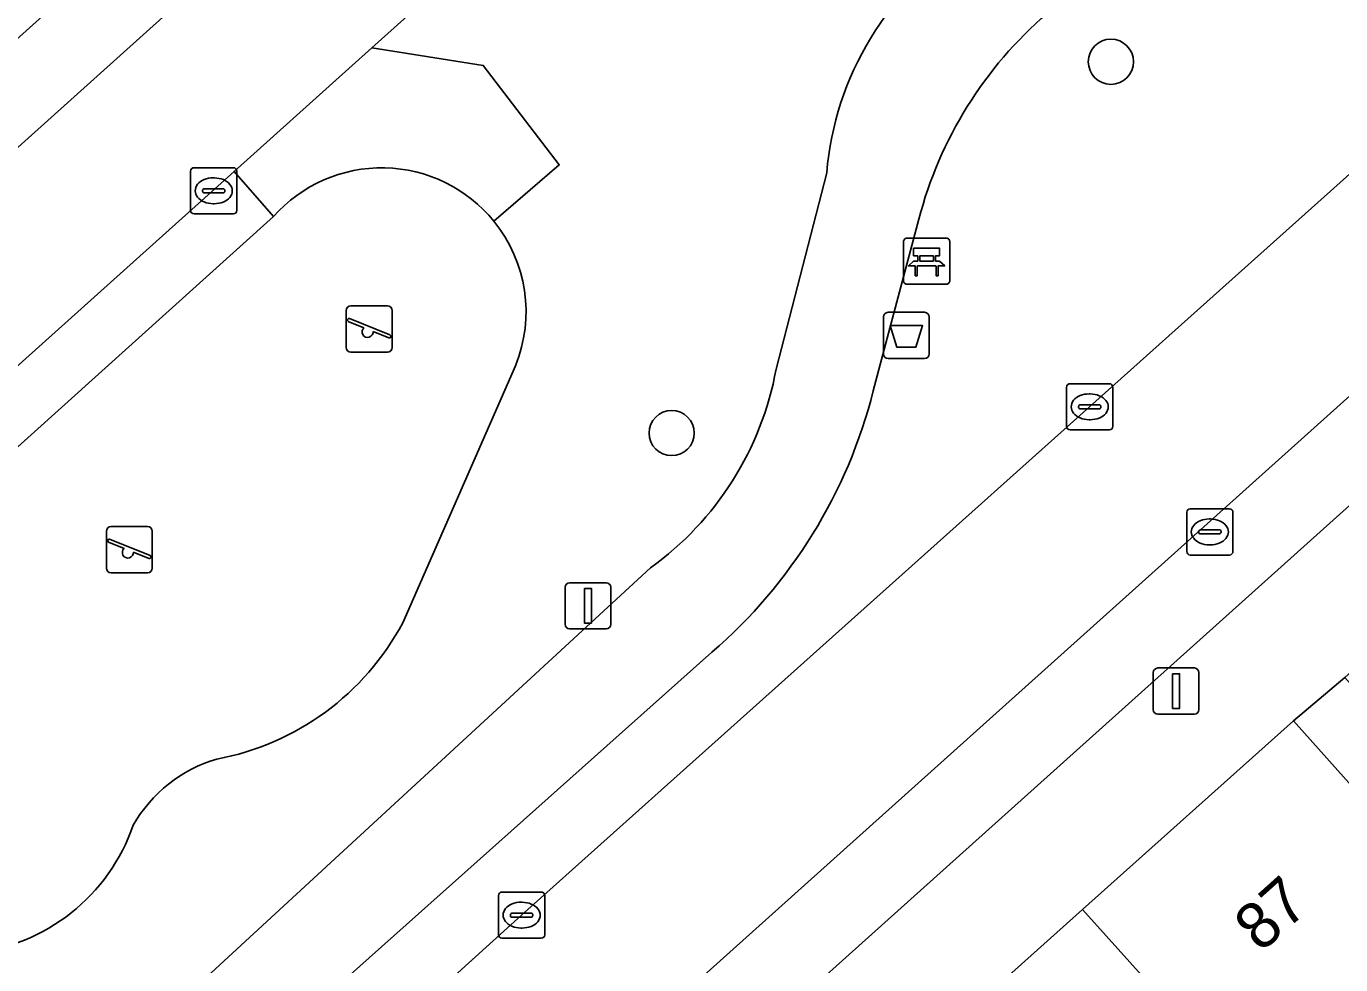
# Model space of a CAD drawing. Extents: x 162172 to 163187, y 382874 to 383685.
# Drawn here: x 162755.23 to 162783.66, y 383328.11 to 383348.42 of the extents above; entities that cross this region are included whole.
import ezdxf

# ---------------------------------------------------------------- set-up
doc = ezdxf.new("R2010")
doc.units = 0
for name, color, linetype in [('IMGEO_Afvalbak', 7, 'Continuous'), ('IMGEO_Bank', 7, 'Continuous'), ('IMGEO_Berm_groen', 7, 'Continuous'), ('IMGEO_Boom', 7, 'Continuous'), ('IMGEO_Groenvoorziening', 7, 'Continuous'), ('IMGEO_Haag', 7, 'Continuous'), ('IMGEO_Kolk', 7, 'Continuous'), ('IMGEO_Lichtmast', 7, 'Continuous'), ('IMGEO_Pand', 7, 'Continuous'), ('IMGEO_Pand_nummerreeks', 7, 'Continuous'), ('IMGEO_Parkeervlak_open', 7, 'Continuous'), ('IMGEO_Rijbaan_lokaal_open', 7, 'Continuous'), ('IMGEO_Speelvoorziening', 7, 'Continuous'), ('IMGEO_Terreindeel_zand', 7, 'Continuous'), ('IMGEO_Voetpad_halfverhard', 7, 'Continuous'), ('IMGEO_Voetpad_open', 7, 'Continuous')]:
    doc.layers.add(name, color=color, linetype=linetype)

msp = doc.modelspace()

# ---------------------------------------------------------------- linework, layer by layer
at = {"layer": 'IMGEO_Afvalbak'}
for p, q in [((162773.773, 383341.333), (162773.773, 383342.133)), ((162773.773, 383342.133), (162773.773, 383341.333)), ((162773.873, 383342.233), (162774.663, 383342.233)), ((162774.663, 383342.233), (162773.873, 383342.233)), ((162774.763, 383342.133), (162774.763, 383341.333)), ((162774.763, 383341.333), (162774.763, 383342.133)), ((162774.663, 383341.233), (162773.873, 383341.233)), ((162773.873, 383341.233), (162774.663, 383341.233))]:
    msp.add_line(p, q, dxfattribs=at)
msp.add_lwpolyline([(162773.916, 383341.947), (162774.62, 383341.947), (162774.471, 383341.477), (162774.065, 383341.477), (162773.916, 383341.947)], dxfattribs=at)
for centre, start, end in [((162773.873, 383342.133), 90, 180), ((162773.873, 383342.133), 90, 180), ((162774.663, 383342.133), 0, 90), ((162774.663, 383342.133), 360, 90), ((162773.873, 383341.333), 180, 270), ((162773.873, 383341.333), 180, 270), ((162774.663, 383341.333), 270, 0), ((162774.663, 383341.333), 270, 0)]:
    msp.add_arc(centre, 0.1, start, end, dxfattribs=at)
at = {"layer": 'IMGEO_Bank'}
for p, q in [((162774.282, 383343.84), (162775.123, 383343.84)), ((162775.123, 383343.84), (162774.282, 383343.84)), ((162774.207, 383342.915), (162774.207, 383343.756)), ((162774.207, 383343.756), (162774.207, 383342.915)), ((162775.207, 383343.765), (162775.207, 383342.924)), ((162775.207, 383342.924), (162775.207, 383343.765)), ((162774.904, 383343.238), (162774.511, 383343.238)), ((162774.516, 383343.346), (162774.516, 383343.452)), ((162774.56, 383343.452), (162774.56, 383343.346)), ((162774.848, 383343.458), (162774.566, 383343.458)), ((162774.566, 383343.34), (162774.848, 383343.34)), ((162774.854, 383343.346), (162774.854, 383343.452)), ((162774.898, 383343.452), (162774.898, 383343.346)), ((162775.132, 383342.84), (162774.291, 383342.84)), ((162774.291, 383342.84), (162775.132, 383342.84))]:
    msp.add_line(p, q, dxfattribs=at)
for points in [[(162774.51, 383343.458), (162774.424, 383343.458), (162774.424, 383343.619), (162774.987, 383343.619), (162774.987, 383343.458), (162774.904, 383343.458)], [(162774.454, 383343.238), (162774.312, 383343.238), (162774.424, 383343.34), (162774.51, 383343.34)], [(162774.504, 383343.231), (162774.504, 383343.024), (162774.461, 383343.024), (162774.461, 383343.231)], [(162774.904, 383343.34), (162774.987, 383343.34), (162775.099, 383343.238), (162774.96, 383343.238)], [(162774.954, 383343.231), (162774.954, 383343.024), (162774.91, 383343.024), (162774.91, 383343.231)]]:
    msp.add_lwpolyline(points, dxfattribs=at)
for centre, radius, start, end in [((162774.285, 383343.762), 0.0779, 92.4484, 184.2845), ((162774.285, 383343.762), 0.0779, 92.4484, 184.2845), ((162775.129, 383343.762), 0.0779, 2.4484, 94.2845), ((162775.129, 383343.762), 0.0779, 2.4484, 94.2845), ((162774.454, 383343.231), 0.00671, 2.8957, 87.1043), ((162774.511, 383343.231), 0.00671, 92.8957, 177.1043), ((162774.509, 383343.451), 0.00671, 2.8957, 87.1043), ((162774.509, 383343.347), 0.00671, 272.8957, 357.1043), ((162774.566, 383343.451), 0.00671, 92.8957, 177.1043), ((162774.566, 383343.347), 0.00671, 182.8957, 267.1043), ((162774.848, 383343.451), 0.00671, 2.8957, 87.1043), ((162774.848, 383343.347), 0.00671, 272.8957, 357.1043), ((162774.905, 383343.451), 0.00671, 92.8957, 177.1043), ((162774.905, 383343.347), 0.00671, 182.8957, 267.1043), ((162774.903, 383343.231), 0.00671, 2.8957, 87.1043), ((162774.96, 383343.231), 0.00671, 92.8957, 177.1043), ((162774.285, 383342.918), 0.0779, 182.4484, 274.2845), ((162774.285, 383342.918), 0.0779, 182.4484, 274.2845), ((162775.129, 383342.918), 0.0779, 272.4484, 4.2845), ((162775.129, 383342.918), 0.0779, 272.4484, 4.2845)]:
    msp.add_arc(centre, radius, start, end, dxfattribs=at)
at = {"layer": 'IMGEO_Berm_groen'}
for points in [[(162744.611, 383310), (162750.185, 383314.921), (162765.945, 383329.187), (162788.183, 383349.104), (162785.604, 383352.953), (162793.329, 383359.988), (162800.361, 383366.393), (162802.051, 383364.873), (162802.602, 383364.378)], [(162767.014, 383351.829), (162765.744, 383350.688), (162762.702, 383347.957), (162765.113, 383347.576), (162766.759, 383345.424), (162765.345, 383344.203)], [(162765.113, 383347.576), (162762.702, 383347.957), (162759.725, 383345.284), (162760.577, 383344.304)], [(162765.345, 383344.203), (162766.759, 383345.424), (162765.113, 383347.576)], [(162771.45, 383341.002), (162772.546, 383345.251)], [(162774.537, 383344.248), (162773.553, 383340.531)], [(162765.813, 383341.076), (162763.374, 383335.515)], [(162752.484, 383321.73), (162768.734, 383336.704)], [(162770.061, 383334.875), (162753.755, 383320.332)]]:
    msp.add_lwpolyline(points, dxfattribs=at)
for centre, radius, start, end in [((162779.19, 383344.699), 6.667, 122.1655, 175.2507), ((162783.057, 383342.031), 8.803, 130.7348, 165.4165), ((162762.918, 383342.241), 3.12, 38.9519, 138.6211), ((162762.923, 383342.242), 3.117, 338.0322, 38.9917), ((162764.766, 383342.219), 6.794, 305.7361, 349.6845), ((162762.811, 383343.257), 11.082, 310.8576, 345.7602), ((162758.299, 383338.215), 5.748, 280.5403, 331.9821), ((162760.223, 383329.601), 3.089, 106.4034, 150.2015), ((162753.628, 383332.479), 4.139, 210.3244, 341.0695)]:
    msp.add_arc(centre, radius, start, end, dxfattribs=at)
at = {"layer": 'IMGEO_Boom'}
for centre in [(162778.692, 383347.656), (162769.191, 383339.62)]:
    msp.add_circle(centre, 0.489, dxfattribs=at)
at = {"layer": 'IMGEO_Groenvoorziening'}
msp.add_lwpolyline([(162760.577, 383344.304), (162759.725, 383345.284), (162749.865, 383336.431), (162750.744, 383335.448)], close=True, dxfattribs=at)
at = {"layer": 'IMGEO_Haag'}
msp.add_lwpolyline([(162760.577, 383344.304), (162759.725, 383345.284), (162749.865, 383336.431), (162750.744, 383335.448)], close=True, dxfattribs=at)
at = {"layer": 'IMGEO_Kolk'}
for p, q in [((162758.784, 383344.437), (162758.784, 383345.289)), ((162758.859, 383345.363), (162759.711, 383345.363)), ((162759.785, 383345.289), (162759.785, 383344.437)), ((162759.272, 383345.143), (162759.297, 383345.143)), ((162759.043, 383344.857), (162759.043, 383344.869)), ((162759.481, 383344.82), (162759.083, 383344.82)), ((162759.086, 383344.906), (162759.484, 383344.906)), ((162759.527, 383344.869), (162759.527, 383344.857)), ((162759.711, 383344.363), (162758.859, 383344.363)), ((162759.295, 383344.583), (162759.27, 383344.583)), ((162777.809, 383340.688), (162778.661, 383340.688)), ((162777.734, 383339.762), (162777.734, 383340.614)), ((162778.222, 383340.468), (162778.247, 383340.468)), ((162778.735, 383340.614), (162778.735, 383339.762)), ((162777.993, 383340.182), (162777.993, 383340.194)), ((162778.431, 383340.145), (162778.033, 383340.145)), ((162778.036, 383340.231), (162778.434, 383340.231)), ((162778.477, 383340.194), (162778.477, 383340.182)), ((162778.245, 383339.908), (162778.22, 383339.908)), ((162778.661, 383339.688), (162777.809, 383339.688)), ((162780.332, 383337.055), (162780.332, 383337.907)), ((162780.407, 383337.981), (162781.259, 383337.981)), ((162781.333, 383337.907), (162781.333, 383337.055)), ((162780.82, 383337.761), (162780.845, 383337.761)), ((162780.591, 383337.475), (162780.591, 383337.487)), ((162781.029, 383337.438), (162780.631, 383337.438)), ((162780.634, 383337.524), (162781.032, 383337.524)), ((162781.075, 383337.487), (162781.075, 383337.475)), ((162781.259, 383336.981), (162780.407, 383336.981)), ((162780.843, 383337.201), (162780.818, 383337.201)), ((162765.444, 383328.761), (162765.444, 383329.613)), ((162765.519, 383329.687), (162766.371, 383329.687)), ((162766.445, 383329.613), (162766.445, 383328.761)), ((162765.932, 383329.467), (162765.957, 383329.467)), ((162765.703, 383329.181), (162765.703, 383329.193)), ((162766.141, 383329.144), (162765.743, 383329.144)), ((162765.746, 383329.23), (162766.144, 383329.23)), ((162766.187, 383329.193), (162766.187, 383329.181)), ((162765.955, 383328.907), (162765.93, 383328.907)), ((162766.371, 383328.687), (162765.519, 383328.687))]:
    msp.add_line(p, q, dxfattribs=at)
for points in [[(162758.784, 383344.437), (162758.784, 383345.289)], [(162758.859, 383345.363), (162759.711, 383345.363)], [(162759.785, 383345.289), (162759.785, 383344.437)], [(162759.711, 383344.363), (162758.859, 383344.363)], [(162777.809, 383340.688), (162778.661, 383340.688)], [(162777.734, 383339.762), (162777.734, 383340.614)], [(162778.735, 383340.614), (162778.735, 383339.762)], [(162778.661, 383339.688), (162777.809, 383339.688)], [(162780.332, 383337.055), (162780.332, 383337.907)], [(162780.407, 383337.981), (162781.259, 383337.981)], [(162781.333, 383337.907), (162781.333, 383337.055)], [(162781.259, 383336.981), (162780.407, 383336.981)], [(162765.444, 383328.761), (162765.444, 383329.613)], [(162765.519, 383329.687), (162766.371, 383329.687)], [(162766.445, 383329.613), (162766.445, 383328.761)], [(162766.371, 383328.687), (162765.519, 383328.687)]]:
    msp.add_lwpolyline(points, dxfattribs=at)
for centre, radius, start, end in [((162758.861, 383345.287), 0.0765, 91.552, 178.448), ((162758.861, 383345.287), 0.0765, 91.552, 178.448), ((162759.709, 383345.287), 0.0765, 1.552, 88.448), ((162759.709, 383345.287), 0.0765, 1.552, 88.448), ((162759.083, 383344.866), 0.0403, 85.8775, 175.7526), ((162759.08, 383344.856), 0.0366, 178.938, 274.7102), ((162759.484, 383344.863), 0.043, 264.8664, 352.4533), ((162759.488, 383344.868), 0.0386, 1.7309, 96.639), ((162758.861, 383344.439), 0.0765, 181.552, 268.448), ((162758.861, 383344.439), 0.0765, 181.552, 268.448), ((162759.709, 383344.439), 0.0765, 271.552, 358.448), ((162759.709, 383344.439), 0.0765, 271.552, 358.448), ((162777.811, 383340.612), 0.0765, 91.552, 178.448), ((162777.811, 383340.612), 0.0765, 91.552, 178.448), ((162778.659, 383340.612), 0.0765, 1.552, 88.448), ((162778.659, 383340.612), 0.0765, 1.552, 88.448), ((162778.033, 383340.191), 0.0403, 85.8775, 175.7526), ((162778.03, 383340.181), 0.0366, 178.938, 274.7102), ((162778.434, 383340.188), 0.043, 264.8664, 352.4533), ((162778.438, 383340.193), 0.0386, 1.7309, 96.639), ((162777.811, 383339.764), 0.0765, 181.552, 268.448), ((162777.811, 383339.764), 0.0765, 181.552, 268.448), ((162778.659, 383339.764), 0.0765, 271.552, 358.448), ((162778.659, 383339.764), 0.0765, 271.552, 358.448), ((162780.409, 383337.905), 0.0765, 91.552, 178.448), ((162780.409, 383337.905), 0.0765, 91.552, 178.448), ((162781.257, 383337.905), 0.0765, 1.552, 88.448), ((162781.257, 383337.905), 0.0765, 1.552, 88.448), ((162780.631, 383337.484), 0.0403, 85.8775, 175.7526), ((162780.628, 383337.474), 0.0366, 178.938, 274.7102), ((162781.032, 383337.481), 0.043, 264.8664, 352.4533), ((162781.036, 383337.486), 0.0386, 1.7309, 96.639), ((162780.409, 383337.057), 0.0765, 181.552, 268.448), ((162780.409, 383337.057), 0.0765, 181.552, 268.448), ((162781.257, 383337.057), 0.0765, 271.552, 358.448), ((162781.257, 383337.057), 0.0765, 271.552, 358.448), ((162765.521, 383329.611), 0.0765, 91.552, 178.448), ((162765.521, 383329.611), 0.0765, 91.552, 178.448), ((162766.369, 383329.611), 0.0765, 1.552, 88.448), ((162766.369, 383329.611), 0.0765, 1.552, 88.448), ((162765.743, 383329.19), 0.0403, 85.8775, 175.7526), ((162765.74, 383329.18), 0.0366, 178.938, 274.7102), ((162766.144, 383329.187), 0.043, 264.8664, 352.4533), ((162766.148, 383329.192), 0.0386, 1.7309, 96.639), ((162765.521, 383328.763), 0.0765, 181.552, 268.448), ((162765.521, 383328.763), 0.0765, 181.552, 268.448), ((162766.369, 383328.763), 0.0765, 271.552, 358.448), ((162766.369, 383328.763), 0.0765, 271.552, 358.448)]:
    msp.add_arc(centre, radius, start, end, dxfattribs=at)
for centre, major_axis, ratio, start_param, end_param in [((162759.271, 383344.863), (-0.387, 0.002), 0.722429, 4.712389, 7.853982), ((162759.296, 383344.863), (-0.39, 0.002), 0.717154, 1.570796, 4.712389), ((162778.221, 383340.188), (-0.387, 0.002), 0.722429, 4.712389, 7.853982), ((162778.246, 383340.188), (-0.39, 0.002), 0.717154, 1.570796, 4.712389), ((162780.819, 383337.481), (-0.387, 0.002), 0.722429, 4.712389, 7.853982), ((162780.844, 383337.481), (-0.39, 0.002), 0.717154, 1.570796, 4.712389), ((162765.931, 383329.187), (-0.387, 0.002), 0.722429, 4.712389, 7.853982), ((162765.956, 383329.187), (-0.39, 0.002), 0.717154, 1.570796, 4.712389)]:
    msp.add_ellipse(centre, major_axis=major_axis, ratio=ratio, start_param=start_param, end_param=end_param, dxfattribs=at)
at = {"layer": 'IMGEO_Lichtmast'}
for p, q in [((162766.884, 383335.482), (162766.884, 383336.282)), ((162766.884, 383336.282), (162766.884, 383335.482)), ((162766.984, 383336.382), (162767.774, 383336.382)), ((162767.774, 383336.382), (162766.984, 383336.382)), ((162767.874, 383336.282), (162767.874, 383335.482)), ((162767.874, 383335.482), (162767.874, 383336.282)), ((162767.774, 383335.382), (162766.984, 383335.382)), ((162766.984, 383335.382), (162767.774, 383335.382)), ((162779.608, 383333.636), (162779.608, 383334.436)), ((162779.608, 383334.436), (162779.608, 383333.636)), ((162779.708, 383334.536), (162780.498, 383334.536)), ((162780.498, 383334.536), (162779.708, 383334.536)), ((162780.598, 383334.436), (162780.598, 383333.636)), ((162780.598, 383333.636), (162780.598, 383334.436)), ((162780.498, 383333.536), (162779.708, 383333.536)), ((162779.708, 383333.536), (162780.498, 383333.536))]:
    msp.add_line(p, q, dxfattribs=at)
for points in [[(162767.304, 383336.257), (162767.454, 383336.257), (162767.454, 383335.507), (162767.304, 383335.507), (162767.304, 383336.257)], [(162780.028, 383334.411), (162780.178, 383334.411), (162780.178, 383333.661), (162780.028, 383333.661), (162780.028, 383334.411)]]:
    msp.add_lwpolyline(points, dxfattribs=at)
for centre, start, end in [((162766.984, 383336.282), 90, 180), ((162766.984, 383336.282), 90, 180), ((162767.774, 383336.282), 0, 90), ((162767.774, 383336.282), 360, 90), ((162766.984, 383335.482), 180, 270), ((162766.984, 383335.482), 180, 270), ((162767.774, 383335.482), 270, 0), ((162767.774, 383335.482), 270, 0), ((162779.708, 383334.436), 90, 180), ((162779.708, 383334.436), 90, 180), ((162780.498, 383334.436), 0, 90), ((162780.498, 383334.436), 360, 90), ((162779.708, 383333.636), 180, 270), ((162779.708, 383333.636), 180, 270), ((162780.498, 383333.636), 270, 0), ((162780.498, 383333.636), 270, 0)]:
    msp.add_arc(centre, 0.1, start, end, dxfattribs=at)
at = {"layer": 'IMGEO_Pand'}
for points in [[(162782.559, 383324.327), (162785.681, 383327.136), (162786.811, 383325.865), (162788.223, 383327.136), (162782.641, 383333.394), (162778.081, 383329.309)], [(162782.559, 383324.327), (162778.081, 383329.309), (162773.633, 383325.324), (162778.663, 383319.729), (162783.078, 383323.703)]]:
    msp.add_lwpolyline(points, close=True, dxfattribs=at)
at = {"layer": 'IMGEO_Parkeervlak_open'}
for points in [[(162736.538, 383329.17), (162736.903, 383329.498), (162763.169, 383353.106), (162788.501, 383375.734), (162792.101, 383379), (162829.073, 383412.003)], [(162825.342, 383411.243), (162737.383, 383332.314)], [(162843.693, 383394.145), (162811.886, 383365.593), (162808.297, 383362.372), (162752.534, 383312.314), (162752.272, 383312.079), (162752.63, 383312.208), (162753.767, 383312.366), (162754.785, 383312.353)], [(162755.461, 383312.558), (162842.607, 383390.811)]]:
    msp.add_lwpolyline(points, dxfattribs=at)
at = {"layer": 'IMGEO_Rijbaan_lokaal_open'}
for points in [[(162765.744, 383350.688), (162767.014, 383351.829), (162784.406, 383367.598), (162789.192, 383371.636), (162790.812, 383373.137), (162788.501, 383375.734), (162763.169, 383353.106), (162736.903, 383329.498), (162739.256, 383327.009), (162745.187, 383332.231), (162745.503, 383332.515), (162749.865, 383336.431), (162759.725, 383345.284), (162762.702, 383347.957)], [(162752.534, 383312.314), (162808.297, 383362.372), (162805.798, 383364.945), (162788.183, 383349.104), (162765.945, 383329.187), (162750.185, 383314.921)]]:
    msp.add_lwpolyline(points, close=True, dxfattribs=at)
at = {"layer": 'IMGEO_Speelvoorziening'}
for p, q in [((162762.252, 383342.372), (162763.042, 383342.372)), ((162763.042, 383342.372), (162762.252, 383342.372)), ((162762.152, 383341.472), (162762.152, 383342.272)), ((162762.152, 383342.272), (162762.152, 383341.472)), ((162762.221, 383342.097), (162763.097, 383341.744)), ((162763.142, 383342.272), (162763.142, 383341.472)), ((162763.142, 383341.472), (162763.142, 383342.272)), ((162762.535, 383341.9), (162762.196, 383342.037)), ((162763.073, 383341.684), (162762.733, 383341.821)), ((162763.042, 383341.372), (162762.252, 383341.372)), ((162762.252, 383341.372), (162763.042, 383341.372)), ((162757.064, 383337.597), (162757.854, 383337.597)), ((162757.854, 383337.597), (162757.064, 383337.597)), ((162756.964, 383336.697), (162756.964, 383337.497)), ((162756.964, 383337.497), (162756.964, 383336.697)), ((162757.347, 383337.125), (162757.008, 383337.262)), ((162757.033, 383337.322), (162757.909, 383336.969)), ((162757.954, 383337.497), (162757.954, 383336.697)), ((162757.954, 383336.697), (162757.954, 383337.497)), ((162757.885, 383336.909), (162757.545, 383337.046)), ((162757.854, 383336.597), (162757.064, 383336.597)), ((162757.064, 383336.597), (162757.854, 383336.597))]:
    msp.add_line(p, q, dxfattribs=at)
for centre, radius, start, end in [((162762.252, 383342.272), 0.1, 90, 180), ((162762.252, 383342.272), 0.1, 90, 180), ((162763.042, 383342.272), 0.1, 0, 90), ((162763.042, 383342.272), 0.1, 360, 90), ((162762.209, 383342.067), 0.0327, 68.078, 248.078), ((162762.614, 383341.81), 0.12, 130.9928, 5.1632), ((162763.085, 383341.714), 0.0327, 248.078, 68.078), ((162762.252, 383341.472), 0.1, 180, 270), ((162762.252, 383341.472), 0.1, 180, 270), ((162763.042, 383341.472), 0.1, 270, 0), ((162763.042, 383341.472), 0.1, 270, 0), ((162757.064, 383337.497), 0.1, 90, 180), ((162757.064, 383337.497), 0.1, 90, 180), ((162757.854, 383337.497), 0.1, 0, 90), ((162757.854, 383337.497), 0.1, 360, 90), ((162757.021, 383337.292), 0.0327, 68.078, 248.078), ((162757.426, 383337.035), 0.12, 130.9928, 5.1632), ((162757.897, 383336.939), 0.0327, 248.078, 68.078), ((162757.064, 383336.697), 0.1, 180, 270), ((162757.064, 383336.697), 0.1, 180, 270), ((162757.854, 383336.697), 0.1, 270, 0), ((162757.854, 383336.697), 0.1, 270, 0)]:
    msp.add_arc(centre, radius, start, end, dxfattribs=at)
at = {"layer": 'IMGEO_Terreindeel_zand'}
for points in [[(162760.577, 383344.304), (162750.744, 383335.448)], [(162763.374, 383335.515), (162765.813, 383341.076)]]:
    msp.add_lwpolyline(points, dxfattribs=at)
for centre, radius, start, end in [((162762.918, 383342.241), 3.12, 38.9519, 138.6211), ((162762.923, 383342.242), 3.117, 338.0322, 38.9917), ((162758.299, 383338.215), 5.748, 280.5403, 331.9821), ((162760.223, 383329.601), 3.089, 106.4034, 150.2015), ((162753.628, 383332.479), 4.139, 210.3244, 341.0695)]:
    msp.add_arc(centre, radius, start, end, dxfattribs=at)
at = {"layer": 'IMGEO_Voetpad_halfverhard'}
for points in [[(162772.546, 383345.251), (162771.45, 383341.002)], [(162773.553, 383340.531), (162774.537, 383344.248)], [(162768.734, 383336.704), (162752.484, 383321.73)], [(162753.755, 383320.332), (162770.061, 383334.875)]]:
    msp.add_lwpolyline(points, dxfattribs=at)
for centre, radius, start, end in [((162779.19, 383344.699), 6.667, 122.1655, 175.2507), ((162783.057, 383342.031), 8.803, 130.7348, 165.4165), ((162764.766, 383342.219), 6.794, 305.7361, 349.6845), ((162762.811, 383343.257), 11.082, 310.8576, 345.7602)]:
    msp.add_arc(centre, radius, start, end, dxfattribs=at)
at = {"layer": 'IMGEO_Voetpad_open'}
for points in [[(162737.383, 383332.314), (162825.342, 383411.243)], [(162842.607, 383390.811), (162755.461, 383312.558)], [(162763.413, 383316.169), (162766.792, 383319.195), (162770.039, 383322.104), (162773.633, 383325.324), (162778.081, 383329.309), (162782.641, 383333.394), (162783.75, 383334.333), (162788.4, 383338.504), (162792.867, 383342.51), (162796.664, 383345.915), (162801.13, 383349.921), (162805.597, 383353.928), (162810.063, 383357.934)], [(162810.153, 383330.878), (162807.919, 383328.875), (162806.356, 383327.473), (162804.123, 383325.469), (162801.89, 383323.466), (162799.657, 383321.463), (162797.183, 383319.264), (162790.015, 383327.327), (162783.75, 383334.333), (162782.641, 383333.394), (162788.223, 383327.136), (162794.092, 383320.435), (162798.526, 383315.447), (162798.702, 383315.578), (162798.801, 383315.502), (162800.173, 383313.968), (162806.783, 383306.582), (162813.788, 383298.759)]]:
    msp.add_lwpolyline(points, dxfattribs=at)

# ---------------------------------------------------------------- texts
at = {"layer": 'IMGEO_Pand_nummerreeks'}
msp.add_text('87', height=1, rotation=41.8551, dxfattribs=at).set_placement((162781.934, 383328.358))

doc.saveas('drawing.dxf')
